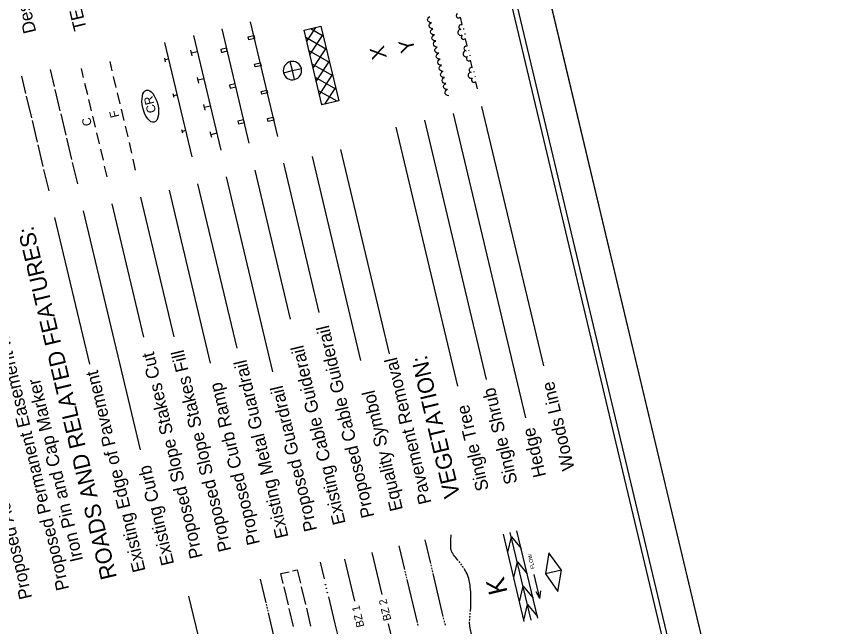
# Model space of a CAD drawing. Extents: x 1734738 to 1742883, y 698103 to 703125.
# Drawn here: x 1739145 to 1740276, y 700083 to 700912 of the extents above; entities that cross this region are included whole.
import ezdxf

# ---------------------------------------------------------------- set-up
doc = ezdxf.new("R2010")
doc.units = 0
for name, color, linetype in [('Exist Road Primary Interstate Shield CELL', 7, 'Continuous'), ('Exist Road Primary US Structure Standard Bridge Number Label', 7, 'Continuous'), ('Exist Road Secondary Structure Pipe Number Label', 7, 'Continuous'), ('Exist Road Secondary Type 41 SR Number Label', 7, 'Continuous'), ('Level 52', 7, 'Continuous')]:
    doc.layers.add(name, color=color, linetype=linetype)

msp = doc.modelspace()

# ---------------------------------------------------------------- linework, layer by layer
at = {"layer": 'Exist Road Primary Interstate Shield CELL'}
for p, q in [((1739703.5, 700907.7), (1739704.1, 700909.5)), ((1739704.1, 700909.5), (1739705.1, 700910.9)), ((1739705.1, 700910.9), (1739706.7, 700911.7)), ((1739750.4, 700901.1), (1739748.1, 700910.8)), ((1739499.9, 700748.9), (1739462.8, 700904.5)), ((1739535.7, 700893.2), (1739558.4, 700898.6)), ((1739558.4, 700898.6), (1739582.6, 700797.3)), ((1739703.9, 700905.9), (1739703.5, 700907.7)), ((1739705.2, 700904.5), (1739703.9, 700905.9)), ((1739706.7, 700903.7), (1739705.2, 700904.5)), ((1739705.5, 700899.5), (1739706.1, 700901.2)), ((1739705.9, 700897.6), (1739705.5, 700899.5)), ((1739707.2, 700896.3), (1739705.9, 700897.6)), ((1739706.1, 700901.2), (1739707.1, 700902.6)), ((1739708.7, 700903.5), (1739706.7, 700903.7)), ((1739707.1, 700902.6), (1739708.6, 700903.4)), ((1739461, 700739.6), (1739423.9, 700895.3)), ((1739559.8, 700791.9), (1739535.7, 700893.2)), ((1739551.1, 700896.9), (1739539.1, 700878.7)), ((1739561.1, 700887.6), (1739543.4, 700860.6)), ((1739561.6, 700885.3), (1739544.2, 700895.3)), ((1739708.7, 700895.4), (1739707.2, 700896.3)), ((1739707.4, 700891.2), (1739708, 700893)), ((1739707.9, 700889.3), (1739707.4, 700891.2)), ((1739709.1, 700888), (1739707.9, 700889.3)), ((1739708, 700893), (1739709.1, 700894.3)), ((1739710.7, 700895.2), (1739708.7, 700895.4)), ((1739709.1, 700894.3), (1739710.6, 700895.1)), ((1739710.7, 700887.1), (1739709.1, 700888)), ((1739712.7, 700887), (1739710.7, 700887.1)), ((1739711, 700886.1), (1739712.6, 700886.9)), ((1739753, 700894.4), (1739752.8, 700895.4)), ((1739754.7, 700887.6), (1739754.4, 700888.6)), ((1739383.2, 700721.1), (1739346.1, 700876.7)), ((1739385, 700886), (1739422.1, 700730.3)), ((1739565.9, 700867.3), (1739538.1, 700883.2)), ((1739709.4, 700882.9), (1739710, 700884.7)), ((1739709.9, 700881.1), (1739709.4, 700882.9)), ((1739711.1, 700879.7), (1739709.9, 700881.1)), ((1739710, 700884.7), (1739711, 700886.1)), ((1739712.6, 700878.9), (1739711.1, 700879.7)), ((1739711.4, 700874.6), (1739712, 700876.4)), ((1739712, 700876.4), (1739713, 700877.8)), ((1739714.6, 700878.7), (1739712.6, 700878.9)), ((1739713, 700877.8), (1739714.6, 700878.6)), ((1739757.4, 700871.9), (1739755.1, 700881.7)), ((1739383.5, 700858.3), (1739381.6, 700866.1)), ((1739390.2, 700864), (1739382.5, 700862.2)), ((1739570.2, 700849.2), (1739542.4, 700865.2)), ((1739565.4, 700869.5), (1739547.7, 700842.6)), ((1739711.8, 700872.8), (1739711.4, 700874.6)), ((1739713.1, 700871.5), (1739711.8, 700872.8)), ((1739714.6, 700870.6), (1739713.1, 700871.5)), ((1739713.4, 700866.4), (1739714, 700868.2)), ((1739713.8, 700864.5), (1739713.4, 700866.4)), ((1739715, 700863.2), (1739713.8, 700864.5)), ((1739714, 700868.2), (1739715, 700869.5)), ((1739716.6, 700870.4), (1739714.6, 700870.6)), ((1739715, 700869.5), (1739716.5, 700870.3)), ((1739760, 700865.3), (1739759.8, 700866.2)), ((1739347.2, 700850.5), (1739346, 700855.4)), ((1739351.5, 700854.1), (1739346.6, 700853)), ((1739716.6, 700862.3), (1739715, 700863.2)), ((1739715.3, 700858.1), (1739715.9, 700859.9)), ((1739715.8, 700856.3), (1739715.3, 700858.1)), ((1739717, 700854.9), (1739715.8, 700856.3)), ((1739715.9, 700859.9), (1739716.9, 700861.3)), ((1739718.6, 700862.2), (1739716.6, 700862.3)), ((1739716.9, 700861.3), (1739718.5, 700862.1)), ((1739718.6, 700854.1), (1739717, 700854.9)), ((1739717.9, 700851.6), (1739718.9, 700853)), ((1739720.5, 700853.9), (1739718.6, 700854.1)), ((1739718.9, 700853), (1739720.5, 700853.8)), ((1739761.6, 700858.5), (1739761.4, 700859.4)), ((1739764.3, 700842.8), (1739762, 700852.5)), ((1739232.3, 700841.4), (1739235.3, 700828.9)), ((1739271.3, 700850.7), (1739274.2, 700838.2)), ((1739519.7, 700838.4), (1739516.8, 700850.5)), ((1739519.7, 700838.4), (1739531.9, 700841.3)), ((1739574.5, 700831.1), (1739546.6, 700847.2)), ((1739569.7, 700851.4), (1739552, 700824.6)), ((1739717.3, 700849.8), (1739717.9, 700851.6)), ((1739717.7, 700848), (1739717.3, 700849.8)), ((1739719, 700846.6), (1739717.7, 700848)), ((1739720.5, 700845.8), (1739719, 700846.6)), ((1739719.3, 700841.6), (1739719.9, 700843.4)), ((1739719.7, 700839.7), (1739719.3, 700841.6)), ((1739719.9, 700843.4), (1739720.9, 700844.7)), ((1739722.5, 700845.6), (1739720.5, 700845.8)), ((1739720.9, 700844.7), (1739722.4, 700845.5)), ((1739157.2, 700807.4), (1739151.7, 700830.7)), ((1739196.2, 700816.6), (1739190.6, 700840)), ((1739276, 700830.6), (1739279.7, 700815.4)), ((1739507.6, 700835.5), (1739519.7, 700838.4)), ((1739522.6, 700826.2), (1739519.7, 700838.4)), ((1739574, 700833.4), (1739556.3, 700806.5)), ((1739721, 700838.4), (1739719.7, 700839.7)), ((1739722.5, 700837.5), (1739721, 700838.4)), ((1739721.2, 700833.3), (1739721.8, 700835.1)), ((1739721.7, 700831.5), (1739721.2, 700833.3)), ((1739722.9, 700830.1), (1739721.7, 700831.5)), ((1739721.8, 700835.1), (1739722.9, 700836.5)), ((1739724.5, 700837.4), (1739722.5, 700837.5)), ((1739722.9, 700836.5), (1739724.4, 700837.3)), ((1739724.5, 700829.2), (1739722.9, 700830.1)), ((1739766.9, 700836.1), (1739766.7, 700837.1)), ((1739768.6, 700829.3), (1739768.3, 700830.2)), ((1739237.1, 700821.4), (1739240.8, 700806.1)), ((1739392.3, 700821.4), (1739390.4, 700829.1)), ((1739399, 700827.1), (1739391.3, 700825.2)), ((1739578.8, 700813.1), (1739551, 700829.1)), ((1739723.2, 700825), (1739723.8, 700826.8)), ((1739723.7, 700823.2), (1739723.2, 700825)), ((1739724.9, 700821.8), (1739723.7, 700823.2)), ((1739723.8, 700826.8), (1739724.8, 700828.2)), ((1739726.5, 700829.1), (1739724.5, 700829.2)), ((1739724.8, 700828.2), (1739726.4, 700829)), ((1739726.4, 700821), (1739724.9, 700821.8)), ((1739725.2, 700816.8), (1739725.8, 700818.6)), ((1739725.8, 700818.6), (1739726.8, 700819.9)), ((1739728.4, 700820.8), (1739726.4, 700821)), ((1739726.8, 700819.9), (1739728.4, 700820.7)), ((1739771.3, 700813.6), (1739769, 700823.3)), ((1739204, 700783.6), (1739197.1, 700812.7)), ((1739281.4, 700808.2), (1739285, 700793.1)), ((1739580.4, 700796.7), (1739555.3, 700811)), ((1739578.3, 700815.3), (1739563.3, 700792.7)), ((1739725.6, 700814.9), (1739725.2, 700816.8)), ((1739726.9, 700813.6), (1739725.6, 700814.9)), ((1739728.4, 700812.7), (1739726.9, 700813.6)), ((1739727.2, 700808.5), (1739727.8, 700810.3)), ((1739727.6, 700806.7), (1739727.2, 700808.5)), ((1739727.8, 700810.3), (1739728.8, 700811.7)), ((1739730.4, 700812.6), (1739728.4, 700812.7)), ((1739728.8, 700811.7), (1739730.3, 700812.4)), ((1739165.1, 700774.3), (1739158.2, 700803.5)), ((1739242.5, 700798.9), (1739246.1, 700783.8)), ((1739358.8, 700801.9), (1739357.6, 700806.7)), ((1739363, 700805.5), (1739358.2, 700804.3)), ((1739582.6, 700797.3), (1739559.8, 700791.9)), ((1739728.8, 700805.3), (1739727.6, 700806.7)), ((1739730.4, 700804.4), (1739728.8, 700805.3)), ((1739732.4, 700804.3), (1739730.4, 700804.4)), ((1739286.7, 700785.9), (1739290.3, 700770.7)), ((1739401.1, 700784.4), (1739399.2, 700792.2)), ((1739407.8, 700790.1), (1739400.1, 700788.3)), ((1739561, 700792.1), (1739559.6, 700792.9)), ((1739777, 700789.5), (1739861, 700437.1)), ((1739211.9, 700750.5), (1739205, 700779.7)), ((1739247.8, 700776.6), (1739251.4, 700761.4)), ((1739738.1, 700780.2), (1739836.7, 700366.4)), ((1739173, 700741.2), (1739166.1, 700770.4)), ((1739292.1, 700763), (1739295.7, 700748.2)), ((1739699.2, 700770.9), (1739783.2, 700418.5)), ((1739253.2, 700753.7), (1739256.8, 700739)), ((1739370.4, 700753.2), (1739369.2, 700758.1)), ((1739374.6, 700756.8), (1739369.8, 700755.7)), ((1739409.9, 700747.4), (1739408, 700755.2)), ((1739416.6, 700753.2), (1739409, 700751.3)), ((1739660.3, 700761.6), (1739744.3, 700409.3)), ((1739219.8, 700717.4), (1739212.8, 700746.6)), ((1739297.5, 700740.6), (1739301, 700726)), ((1739180.9, 700708.1), (1739173.9, 700737.3)), ((1739258.6, 700731.4), (1739262.1, 700716.7)), ((1739585.2, 700731.1), (1739651.3, 700453.6)), ((1739306.4, 700703.1), (1739302.9, 700717.9)), ((1739546.3, 700721.8), (1739612.4, 700444.4)), ((1739227.7, 700684.3), (1739220.7, 700713.5)), ((1739267.5, 700693.8), (1739264, 700708.6)), ((1739507.4, 700712.6), (1739555.7, 700509.7)), ((1739188.8, 700675.1), (1739181.8, 700704.2)), ((1739429.5, 700694), (1739492.7, 700429)), ((1739468.5, 700703.3), (1739516.8, 700500.4)), ((1739390.6, 700684.7), (1739443.9, 700461.3)), ((1739351.9, 700675.8), (1739408, 700440.6)), ((1739313, 700666.6), (1739358.3, 700476.4)), ((1739274.1, 700657.3), (1739317.3, 700476)), ((1739196.2, 700638.7), (1739243.7, 700439.6)), ((1739235.2, 700648), (1739312.7, 700322.8)), ((1739834.9, 700089.9), (1739806.7, 700208.6)), ((1739844.4, 700091.6), (1739816, 700210.8)), ((1739853.3, 700094.2), (1739825, 700212.9)), ((1739707.7, 700168.6), (1739700.1, 700200.7)), ((1739812.6, 700183.8), (1739817.4, 700204.7)), ((1739817.4, 700204.7), (1739830.8, 700188.7)), ((1739672.5, 700160.2), (1739664.8, 700192.3)), ((1739590.6, 700174.6), (1739604.2, 700117.5)), ((1739627.5, 700183.4), (1739641.1, 700126.3)), ((1739868.6, 700182.9), (1739864, 700154.5)), ((1739885.5, 700159.6), (1739868.6, 700182.9)), ((1739708.7, 700164.7), (1739708.2, 700166.7)), ((1739709.6, 700160.8), (1739709.1, 700162.8)), ((1739749.9, 700166.4), (1739748.7, 700168)), ((1739752.2, 700163.1), (1739751, 700164.8)), ((1739820.8, 700149.3), (1739825.6, 700170.7)), ((1739825.6, 700170.7), (1739839, 700154.4)), ((1739673.4, 700156.3), (1739672.9, 700158.3)), ((1739674.3, 700152.4), (1739673.9, 700154.4)), ((1739710.5, 700156.9), (1739710, 700158.9)), ((1739724.9, 700096.6), (1739711, 700155)), ((1739856.2, 700121.1), (1739848.5, 700153.5)), ((1739885.5, 700159.6), (1739864, 700154.5)), ((1739864, 700154.5), (1739880.6, 700130.5)), ((1739880.6, 700130.5), (1739885.5, 700159.6)), ((1739483.9, 700115.2), (1739476.2, 700147.3)), ((1739675.3, 700148.5), (1739674.8, 700150.5)), ((1739689.6, 700088.2), (1739675.7, 700146.6)), ((1739514.2, 700112.3), (1739508.4, 700136.6)), ((1739531.6, 700136.9), (1739537.4, 700112.6)), ((1739828.6, 700116.3), (1739833.4, 700137.6)), ((1739833.4, 700137.6), (1739846.9, 700121.3)), ((1739856.2, 700121.1), (1739851.3, 700129.8)), ((1739856.2, 700121.1), (1739857.7, 700131.4)), ((1739416, 699968.5), (1739378.9, 700124.1)), ((1739484.8, 700111.4), (1739484.3, 700113.3)), ((1739485.7, 700107.5), (1739485.2, 700109.4)), ((1739521.2, 700083.1), (1739515.4, 700107.4)), ((1739538.6, 700107.8), (1739544.4, 700083.4)), ((1739834.5, 700091.6), (1739839.3, 700112.9)), ((1739839.3, 700112.9), (1739852.8, 700096.5)), ((1739486.6, 700103.6), (1739486.2, 700105.5)), ((1739501, 700043.3), (1739487.1, 700101.6)), ((1739725.8, 700092.7), (1739725.3, 700094.7)), ((1739761.4, 700099.1), (1739761.6, 700101.1)), ((1739665.7, 700022.8), (1739650.5, 700086.7)), ((1739690.6, 700084.3), (1739690.1, 700086.3)), ((1739726.7, 700088.8), (1739726.3, 700090.8)), ((1739727.7, 700084.9), (1739727.2, 700086.9))]:
    msp.add_line(p, q, dxfattribs=at)
for points in [[(1737411.4, 701976.4), (1738106.9, 699058.2), (1740147.7, 699544.6), (1739452.2, 702462.8)], [(1739460.4, 700880.2), (1739459.4, 700884.1), (1739467.2, 700886), (1739468.1, 700882.1)], [(1739431.1, 700865.1), (1739430.2, 700868.9), (1739422.4, 700867.1), (1739423.3, 700863.2)], [(1739469.2, 700843.3), (1739468.3, 700847.2), (1739476, 700849), (1739477, 700845.1)], [(1739442.7, 700816.4), (1739441.8, 700820.3), (1739434, 700818.4), (1739434.9, 700814.6)], [(1739478, 700806.3), (1739477.1, 700810.2), (1739484.8, 700812), (1739485.8, 700808.2)], [(1739486.8, 700769.3), (1739485.9, 700773.2), (1739493.7, 700775.1), (1739494.6, 700771.2)], [(1739454.3, 700767.8), (1739453.3, 700771.7), (1739445.6, 700769.8), (1739446.5, 700765.9)]]:
    msp.add_lwpolyline(points, close=True, dxfattribs=at)
for points in [[(1739745, 700172.8), (1739744.3, 700173.6), (1739741.4, 700176.9), (1739740, 700178.6), (1739738.7, 700180.5), (1739737.8, 700181.9), (1739737.1, 700183.1), (1739736.6, 700184.3), (1739736.2, 700185.3), (1739735.6, 700187.2), (1739735.3, 700188.6), (1739735.1, 700189.7), (1739734.9, 700191.3), (1739734.9, 700192.9), (1739735.2, 700200.3), (1739735.4, 700207.6)], [(1739563.2, 700147.9), (1739557.9, 700170.2)], [(1739747.5, 700169.6), (1739747.2, 700170), (1739746.3, 700171.2)], [(1739507.3, 700141.5), (1739504.1, 700154.7), (1739515.1, 700157.4)], [(1739520, 700158.5), (1739526.1, 700160), (1739530.5, 700141.8)], [(1739761.8, 700103.1), (1739761.9, 700104.7), (1739762.1, 700107.6), (1739762.2, 700113.2), (1739762.3, 700117.4), (1739762.2, 700123.6), (1739762.1, 700129.9), (1739761.9, 700133.3), (1739761.6, 700136.3), (1739761.3, 700139), (1739760.9, 700141.3), (1739760.6, 700143.3), (1739760.2, 700145), (1739759.4, 700148.1), (1739758.7, 700150.3), (1739758.1, 700151.9), (1739757.2, 700154.4), (1739756, 700156.7), (1739755.1, 700158.5), (1739754.2, 700160), (1739753.2, 700161.5)], [(1739577.9, 700086.5), (1739569.1, 700123.4)], [(1739761, 700095.2), (1739761.1, 700096), (1739761.2, 700097.2)], [(1739584.4, 700059.2), (1739577.9, 700086.5)], [(1739760.7, 700091.2), (1739760.8, 700092.1), (1739760.8, 700093.2)], [(1739777.2, 700049.4), (1739773.6, 700054.4), (1739770, 700059.4), (1739769.1, 700060.7), (1739767.7, 700062.9), (1739766.7, 700064.7), (1739765.4, 700067.4), (1739764.2, 700070.1), (1739763.3, 700072.5), (1739762.6, 700074.6), (1739762.1, 700076.4), (1739761.7, 700078.1), (1739761.2, 700081), (1739760.9, 700083.2), (1739760.8, 700084.9), (1739760.7, 700087.4), (1739760.7, 700089.2)]]:
    msp.add_lwpolyline(points, dxfattribs=at)
for centre, radius, start, end in [((1739745.5, 700913.2), 3.16, 121.8409, 322.6374), ((1739749.2, 700897.6), 3.16, 64.1744, 264.971), ((1739748.8, 700890.4), 4.12, 89.3697, 297.4422), ((1739752.4, 700884), 3.16, 121.8409, 322.6374), ((1739755.8, 700861.2), 4.12, 89.3697, 297.4422), ((1739756.1, 700868.4), 3.16, 64.1744, 264.971), ((1739759.4, 700854.8), 3.16, 121.8409, 322.6374), ((1739519.7, 700838.4), 12.5, 103.4003, 193.4048), ((1739519.7, 700838.4), 12.5, 13.4003, 103.4048), ((1739519.7, 700838.4), 12.5, 283.4003, 13.4048), ((1739763.1, 700839.3), 3.16, 64.1744, 264.971), ((1739519.7, 700838.4), 12.5, 193.4003, 283.4048), ((1739762.7, 700832), 4.12, 89.3697, 297.4422), ((1739766.3, 700825.6), 3.16, 121.8409, 322.6374)]:
    msp.add_arc(centre, radius, start, end, dxfattribs=at)
for centre in [(1739564.6, 700139.8), (1739565.8, 700134.8), (1739567.2, 700129)]:
    msp.add_ellipse(centre, major_axis=(-0.383, -0.091), ratio=0.938496, dxfattribs=at)
at = {"layer": 'Exist Road Primary US Structure Standard Bridge Number Label'}
msp.add_line((1740275.8, 699231.7), (1739494.9, 702508), dxfattribs=at)
at = {"layer": 'Exist Road Secondary Structure Pipe Number Label'}
msp.add_lwpolyline([(1740226.1, 699246.6), (1739453.3, 702488.8), (1737400.6, 701999.6), (1738173.4, 698757.4)], close=True, dxfattribs=at)
at = {"layer": 'Exist Road Secondary Type 41 SR Number Label'}
msp.add_lwpolyline([(1740275.8, 699231.7), (1739494.9, 702508), (1737354.8, 701997.9), (1738135.7, 698721.7)], close=True, dxfattribs=at)
at = {"layer": 'Level 52'}
msp.add_ellipse((1739326.4, 700790), major_axis=(-5.2, 21.8), ratio=0.462467, dxfattribs=at)

# ---------------------------------------------------------------- texts
at = {"layer": 'Exist Road Primary Interstate Shield CELL'}
for s, height, p in [('Designated U/G Power Line (S.U.E.*)', 17.5, (1739171.4, 700891.1)), ('TELEPHONE:', 17.5, (1739240, 700895)), ('Y', 20, (1739687, 700865.4)), ('X', 20, (1739648.1, 700856.2)), ('C', 11.9, (1739247.1, 700764.6)), ('F', 11.9, (1739284.2, 700775.9)), ('ROADS AND RELATED FEATURES:', 22, (1739281.1, 700149.6)), ('Proposed Permanent Easement with', 17.5, (1739216.1, 700134.1)), ('Proposed Cable Guiderail', 17.5, (1739631.1, 700232.7)), ('Proposed Slope Stakes Cut', 17.5, (1739397.8, 700177.4)), ('Proposed Slope Stakes Fill', 17.5, (1739436.7, 700186.7)), ('Existing Cable Guiderail', 17.5, (1739592.2, 700223.4)), ('Proposed Aerial Utility Easement', 17.5, (1739165.8, 700122.1)), ('Pavement Removal', 17.5, (1739708.9, 700251.2)), ('VEGETATION:', 22, (1739748, 700260.5)), ('Existing Metal Guardrail', 17.5, (1739514.4, 700204.9)), ('Existing Edge of Pavement', 17.5, (1739320, 700158.9)), ('Iron Pin and Cap Marker', 17.5, (1739235.1, 700173.1)), ('Proposed Curb Ramp', 17.5, (1739475.6, 700195.9)), ('Woods Line', 17.5, (1739903.7, 700297.1)), ('Proposed Guardrail', 17.5, (1739553.3, 700214.2)), ('Equality Symbol', 17.5, (1739670, 700242)), ('Single Shrub', 17.5, (1739825.9, 700278.5)), ('Single Tree', 17.5, (1739787, 700269.3)), ('Hedge', 17.5, (1739864.8, 700287.8)), ('Existing Curb', 17.5, (1739358.9, 700168.1)), ('FLOW', 5.19, (1739849.3, 700161.8)), ('K', 25.5, (1739812.4, 700129.5)), ('BZ 2', 10.63, (1739654.3, 700092)), ('BZ 1', 10.63, (1739617.5, 700083.2))]:
    msp.add_text(s, height=height, rotation=103.4059, dxfattribs=at).set_placement(p)
at = {"layer": 'Level 52'}
msp.add_text('CR', height=12, rotation=103.4059, dxfattribs=at).set_placement((1739334.4, 700782.2))

doc.saveas('drawing.dxf')
